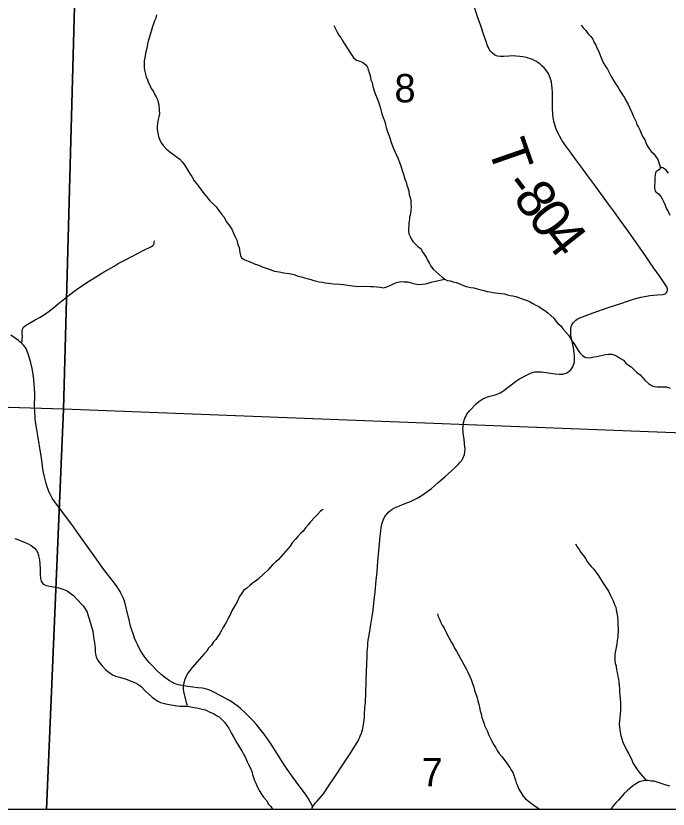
# Model space of a CAD drawing. Extents: x -3.3 to 34, y 0 to 56.8.
# Drawn here: x -0.484 to 0.477, y 28.077 to 29.247 of the extents above; entities that cross this region are included whole.
import ezdxf

# ---------------------------------------------------------------- set-up
doc = ezdxf.new("R2010")
doc.units = 0
for name, color, linetype in [('GM_X_Corporation', 7, 'Continuous'), ('GM_X_Section_Text', 7, 'Continuous'), ('GM_X_Township_Road', 7, 'Continuous'), ('GM_X_Township_Road_Text', 7, 'Continuous'), ('GT_Project_Soil_Layers', 7, 'Continuous'), ('SH_Data', 7, 'Continuous')]:
    doc.layers.add(name, color=color, linetype=linetype)

msp = doc.modelspace()

# ---------------------------------------------------------------- linework, layer by layer
at = {"layer": 'GM_X_Corporation'}
msp.add_lwpolyline([(-3.3039, 33.7379), (-3.3039, 28.0771), (1.5699, 28.0771), (1.5942, 28.7382), (1.6459, 29.8169), (1.6538, 30.0279), (1.685, 30.798), (1.6882, 30.9891), (1.6883, 30.9953), (1.6885, 31.0075), (1.698, 31.5661), (1.7459, 32.363)], dxfattribs=at)
for points in [[(-1.3918, 29.7067), (-0.3862, 29.675), (-0.4137, 28.6668), (-1.4193, 28.6974)], [(0.6247, 29.6418), (0.5878, 28.6278), (-0.4137, 28.6668), (-0.3862, 29.675)], [(-1.4478, 28.0771), (-0.4384, 28.0771), (-0.4137, 28.6668), (-1.4193, 28.6974)], [(-0.4384, 28.0771), (0.5667, 28.0771), (0.5878, 28.6278), (-0.4137, 28.6668)]]:
    msp.add_lwpolyline(points, close=True, dxfattribs=at)
at = {"layer": 'GM_X_Township_Road'}
for points in [[(-0.0464, 28.0803), (-0.0453, 28.0823), (-0.0437, 28.0845), (-0.0421, 28.0862), (-0.0399, 28.0886), (-0.0369, 28.092), (-0.0306, 28.0998), (-0.024, 28.1093), (-0.0127, 28.1263), (-0.0024, 28.1419), (0.0084, 28.1581), (0.0191, 28.1751), (0.0212, 28.1788), (0.0237, 28.1844), (0.0254, 28.1892), (0.0273, 28.1957), (0.0281, 28.199), (0.0291, 28.2055), (0.0298, 28.2122), (0.0302, 28.2169), (0.0307, 28.2257), (0.0313, 28.2348), (0.0318, 28.2481), (0.0325, 28.2655), (0.0331, 28.2799), (0.0339, 28.3033), (0.0341, 28.3086), (0.0345, 28.3134), (0.0347, 28.3174), (0.035, 28.3211), (0.0356, 28.3263), (0.0368, 28.3338), (0.0394, 28.3493), (0.0414, 28.361), (0.0426, 28.3703), (0.0438, 28.3807), (0.0456, 28.3976), (0.0473, 28.4143), (0.0485, 28.427), (0.0498, 28.4428), (0.0514, 28.4627), (0.053, 28.4797), (0.0539, 28.4876), (0.0546, 28.4924), (0.0557, 28.4971), (0.0571, 28.5017), (0.0582, 28.5048), (0.0597, 28.5078), (0.0614, 28.5104), (0.0627, 28.512), (0.0658, 28.5153), (0.0683, 28.5174), (0.0706, 28.5191), (0.0741, 28.5211), (0.0815, 28.5244), (0.091, 28.5282), (0.0951, 28.5297), (0.0985, 28.5312), (0.1034, 28.5335), (0.1075, 28.5357), (0.1151, 28.5402), (0.1185, 28.5425), (0.1238, 28.5463), (0.1285, 28.55), (0.1383, 28.5586), (0.1482, 28.5672), (0.1584, 28.576), (0.1645, 28.5816), (0.1681, 28.5852), (0.1706, 28.588), (0.1727, 28.5908), (0.1748, 28.5941), (0.1759, 28.5964), (0.1771, 28.6001), (0.1778, 28.6039), (0.1781, 28.6077), (0.1779, 28.6108), (0.1775, 28.6162), (0.1767, 28.6225), (0.1759, 28.6279), (0.1755, 28.6314), (0.1753, 28.6348), (0.1751, 28.638), (0.1752, 28.641), (0.1755, 28.645), (0.1761, 28.6479), (0.1768, 28.6507), (0.178, 28.6537), (0.1791, 28.6562), (0.1805, 28.6585), (0.1824, 28.6612), (0.1852, 28.6647), (0.1946, 28.6745), (0.1985, 28.678), (0.2014, 28.6801), (0.2044, 28.6819), (0.2079, 28.6835), (0.2129, 28.6854), (0.2188, 28.6869), (0.2225, 28.6878), (0.2253, 28.6887), (0.2278, 28.6898), (0.2301, 28.6909), (0.2323, 28.6922), (0.2352, 28.6945), (0.2461, 28.7029), (0.2525, 28.7076), (0.2585, 28.7114), (0.2706, 28.7179), (0.2737, 28.7194), (0.2761, 28.7204), (0.2788, 28.7212), (0.281, 28.7216), (0.2838, 28.7218), (0.287, 28.7218), (0.2905, 28.7216), (0.2944, 28.7213), (0.3111, 28.719), (0.3166, 28.7185), (0.3188, 28.7184), (0.3221, 28.7186), (0.325, 28.7193), (0.3269, 28.72), (0.3288, 28.7209), (0.3309, 28.7223), (0.3331, 28.7239), (0.3352, 28.7263), (0.3369, 28.7291), (0.3381, 28.7324), (0.3388, 28.7348), (0.3392, 28.7372), (0.3394, 28.7412), (0.3394, 28.745), (0.339, 28.7498), (0.3379, 28.7574), (0.3364, 28.7646), (0.3352, 28.7705), (0.3342, 28.7762), (0.3338, 28.78), (0.3339, 28.7856), (0.3345, 28.7884), (0.3356, 28.7909), (0.3375, 28.7939), (0.3394, 28.796), (0.3412, 28.7978), (0.3433, 28.7995), (0.3452, 28.8006), (0.3473, 28.8014), (0.3667, 28.8087), (0.389, 28.8165), (0.406, 28.8223), (0.4191, 28.8267), (0.4278, 28.8293), (0.437, 28.8318), (0.4456, 28.8336), (0.4506, 28.8343), (0.456, 28.8349), (0.4612, 28.8353), (0.4697, 28.8359), (0.4716, 28.8363), (0.4729, 28.8367), (0.474, 28.8376), (0.4749, 28.8387), (0.4758, 28.8405), (0.4763, 28.8424), (0.4764, 28.8441), (0.4761, 28.8456), (0.4756, 28.847), (0.4747, 28.8486), (0.4714, 28.8533), (0.4642, 28.8637), (0.4565, 28.8748), (0.4501, 28.8841), (0.4451, 28.8914), (0.4362, 28.9041), (0.4258, 28.9189), (0.4175, 28.9307), (0.4069, 28.9456), (0.3983, 28.9574), (0.3897, 28.969), (0.3792, 28.9834), (0.3687, 28.9977), (0.3588, 29.0111), (0.3497, 29.0235), (0.3409, 29.0355), (0.332, 29.0477), (0.3249, 29.0573), (0.323, 29.06), (0.3214, 29.0626), (0.3179, 29.0686), (0.3161, 29.0718), (0.3145, 29.0752), (0.312, 29.0809), (0.3108, 29.0845), (0.3098, 29.0879), (0.3091, 29.0907), (0.3086, 29.0937), (0.3081, 29.0966), (0.3075, 29.1019), (0.3072, 29.1099), (0.307, 29.125), (0.3069, 29.1342), (0.3066, 29.1401), (0.3062, 29.1444), (0.3055, 29.1487), (0.3047, 29.1522), (0.3038, 29.1551), (0.3027, 29.1579), (0.3009, 29.1615), (0.2992, 29.1643), (0.2973, 29.1671), (0.2947, 29.17), (0.2915, 29.1732), (0.2887, 29.1755), (0.2859, 29.1776), (0.2835, 29.1792), (0.281, 29.1806), (0.2775, 29.1823), (0.2745, 29.1835), (0.2713, 29.1845), (0.2685, 29.1852), (0.2635, 29.1862), (0.2591, 29.1869), (0.2536, 29.1875), (0.2499, 29.1876), (0.2353, 29.1869), (0.2325, 29.1868), (0.2297, 29.1869), (0.226, 29.1875), (0.2236, 29.1884), (0.2216, 29.1894), (0.2179, 29.192), (0.2155, 29.1948), (0.2141, 29.1968), (0.2125, 29.1999), (0.2113, 29.2026), (0.2097, 29.2073), (0.2054, 29.2199), (0.2013, 29.2319), (0.1967, 29.2453), (0.1914, 29.261)], [(-0.4757, 28.7643), (-0.4747, 28.7673), (-0.4743, 28.7699), (-0.4742, 28.7735), (-0.4744, 28.7787), (-0.4744, 28.7815), (-0.4742, 28.7838), (-0.4736, 28.7855), (-0.4723, 28.7875), (-0.47, 28.7897), (-0.4672, 28.7917), (-0.4553, 28.7985), (-0.4481, 28.8025), (-0.4416, 28.8065), (-0.4348, 28.8114), (-0.4279, 28.8167), (-0.4213, 28.8222), (-0.4117, 28.8301), (-0.3984, 28.8405), (-0.3931, 28.8444), (-0.3872, 28.8483), (-0.3777, 28.8543), (-0.3678, 28.8605), (-0.357, 28.8674), (-0.3391, 28.8778), (-0.3328, 28.8815), (-0.3234, 28.8867), (-0.313, 28.892), (-0.3036, 28.8968), (-0.2964, 28.9007), (-0.2839, 28.9068), (-0.2821, 28.908), (-0.2809, 28.9093), (-0.2801, 28.9109), (-0.2798, 28.9129), (-0.2796, 28.9152)], [(-0.0464, 28.0803), (-0.0501, 28.0876), (-0.0532, 28.0933), (-0.0559, 28.0975), (-0.0584, 28.1009), (-0.0692, 28.1155), (-0.0779, 28.1276), (-0.0872, 28.1409), (-0.1076, 28.1729), (-0.1177, 28.1874), (-0.1298, 28.2021), (-0.1338, 28.2066), (-0.146, 28.2188), (-0.1527, 28.2253), (-0.1561, 28.2283), (-0.161, 28.2319), (-0.1649, 28.2346), (-0.1691, 28.237), (-0.1919, 28.2494), (-0.1968, 28.2519), (-0.2008, 28.2534), (-0.2046, 28.2544), (-0.2087, 28.2552), (-0.2155, 28.2561), (-0.2306, 28.2579), (-0.2416, 28.2596), (-0.2446, 28.2603), (-0.2474, 28.2611), (-0.2507, 28.2625), (-0.2531, 28.2637), (-0.2575, 28.2664), (-0.2629, 28.2701), (-0.2696, 28.2756), (-0.2764, 28.2822), (-0.2831, 28.289), (-0.2872, 28.2932), (-0.2917, 28.2985), (-0.2949, 28.3026), (-0.2968, 28.3055), (-0.2996, 28.31), (-0.302, 28.3144), (-0.3041, 28.3186), (-0.3065, 28.3239), (-0.3088, 28.3293), (-0.311, 28.3354), (-0.3133, 28.3422), (-0.3147, 28.3467), (-0.3163, 28.3537), (-0.3203, 28.3701), (-0.3213, 28.374), (-0.3234, 28.3824), (-0.3252, 28.3876), (-0.3269, 28.3917), (-0.3289, 28.3956), (-0.3303, 28.398), (-0.332, 28.4007), (-0.3346, 28.4048), (-0.3383, 28.4101), (-0.354, 28.4302), (-0.3722, 28.456), (-0.3908, 28.4821), (-0.4015, 28.4967), (-0.4267, 28.5306), (-0.4302, 28.5358), (-0.4317, 28.5384), (-0.4322, 28.5393), (-0.4338, 28.5425), (-0.4356, 28.5467), (-0.4376, 28.5521), (-0.4391, 28.557), (-0.4418, 28.5672), (-0.4432, 28.5734), (-0.4439, 28.5786), (-0.4461, 28.5952), (-0.4473, 28.6035), (-0.4509, 28.6252), (-0.453, 28.6366), (-0.4548, 28.6481), (-0.4554, 28.6531), (-0.456, 28.6641), (-0.4561, 28.6694), (-0.4559, 28.6892), (-0.4562, 28.6976), (-0.4571, 28.7089), (-0.4578, 28.7151), (-0.4587, 28.7211), (-0.4597, 28.7269), (-0.4616, 28.7353), (-0.4635, 28.7421), (-0.4656, 28.7486), (-0.4669, 28.752), (-0.4688, 28.756), (-0.4702, 28.7582), (-0.4725, 28.7612), (-0.4757, 28.7643), (-0.4777, 28.766), (-0.4801, 28.7678), (-0.4911, 28.7759)], [(-0.0473, 28.0771), (-0.047, 28.079), (-0.0464, 28.0803)]]:
    msp.add_lwpolyline(points, dxfattribs=at)
at = {"layer": 'GT_Project_Soil_Layers'}
for points in [[(-0.2765, 29.2484), (-0.2776, 29.2434), (-0.2795, 29.2396), (-0.2809, 29.2347), (-0.2824, 29.2309), (-0.2838, 29.2255), (-0.2856, 29.2206), (-0.2889, 29.2095), (-0.29, 29.2053), (-0.2903, 29.2015), (-0.2914, 29.1973), (-0.2921, 29.1935), (-0.2935, 29.1852), (-0.2946, 29.1806), (-0.2945, 29.1711), (-0.294, 29.1666), (-0.2932, 29.1628), (-0.292, 29.1567), (-0.29, 29.1526), (-0.2889, 29.1488), (-0.2865, 29.1443), (-0.2842, 29.1394), (-0.2811, 29.1353), (-0.2795, 29.1311), (-0.2772, 29.1273), (-0.2752, 29.1232), (-0.274, 29.119), (-0.2732, 29.1153), (-0.2724, 29.1077), (-0.2723, 29.102), (-0.273, 29.0978), (-0.2744, 29.0917), (-0.2751, 29.0879), (-0.2755, 29.0837), (-0.2754, 29.0792), (-0.2734, 29.069), (-0.2714, 29.0633), (-0.2694, 29.0592), (-0.2667, 29.0554), (-0.2617, 29.0502), (-0.2568, 29.0461), (-0.2476, 29.0394), (-0.2422, 29.0353), (-0.238, 29.0311), (-0.236, 29.0274), (-0.2326, 29.0229), (-0.2294, 29.0172), (-0.2271, 29.0135), (-0.2244, 29.0097), (-0.2209, 29.0033), (-0.2178, 28.9995), (-0.2147, 28.9954), (-0.2066, 28.9849), (-0.2032, 28.9808), (-0.1978, 28.974), (-0.1935, 28.9699), (-0.1893, 28.9654), (-0.1847, 28.9598), (-0.1808, 28.9545), (-0.177, 28.95), (-0.1738, 28.9436), (-0.17, 28.9387), (-0.1657, 28.932), (-0.163, 28.9263), (-0.1603, 28.9199), (-0.1583, 28.9161), (-0.1567, 28.9097), (-0.1547, 28.9052), (-0.1535, 28.898), (-0.1527, 28.8935), (-0.1511, 28.8897), (-0.1462, 28.8871), (-0.1416, 28.8849), (-0.1374, 28.8834), (-0.1309, 28.8805), (-0.1256, 28.879), (-0.1206, 28.8768), (-0.1149, 28.8746), (-0.1092, 28.8728), (-0.1027, 28.8703), (-0.0959, 28.8692), (-0.089, 28.8678), (-0.0807, 28.8668), (-0.0742, 28.8653), (-0.0677, 28.8628), (-0.0628, 28.8617), (-0.0586, 28.8602), (-0.0525, 28.8592), (-0.0411, 28.8556), (-0.0369, 28.8545), (-0.032, 28.8538), (-0.0278, 28.8531), (-0.0232, 28.8528), (-0.0194, 28.8521), (-0.0156, 28.8517), (-0.0065, 28.8511), (-0.0012, 28.8508), (0.0049, 28.8497), (0.0087, 28.849)], [(-0.0151, 29.2323), (-0.0104, 29.2225), (-0.008, 29.2184), (-0.005, 29.2146), (-0.003, 29.2108), (-0.0007, 29.2067), (0.0024, 29.2026), (0.0047, 29.1984), (0.0082, 29.1932), (0.0113, 29.1887), (0.014, 29.1849), (0.0182, 29.1815), (0.0232, 29.1797), (0.0274, 29.1779), (0.0316, 29.1749), (0.0343, 29.1711), (0.0355, 29.167), (0.0367, 29.1632), (0.0383, 29.1587), (0.0395, 29.1522), (0.0411, 29.1485), (0.0423, 29.1424), (0.0454, 29.1333), (0.0486, 29.125), (0.0509, 29.1186), (0.0521, 29.1148), (0.0533, 29.1103), (0.0557, 29.1024), (0.0577, 29.0967), (0.06, 29.0907), (0.0609, 29.0858), (0.0621, 29.082), (0.0632, 29.0774), (0.0656, 29.0706), (0.0672, 29.0669), (0.0692, 29.0601), (0.0715, 29.0537), (0.0747, 29.0465), (0.0774, 29.0405), (0.0797, 29.0359), (0.0809, 29.0322), (0.0837, 29.0254), (0.0857, 29.0186), (0.0876, 29.0133), (0.0892, 29.0057), (0.0912, 29.0016), (0.0924, 28.997), (0.0944, 28.9917), (0.0952, 28.988), (0.096, 28.983), (0.0972, 28.9789), (0.098, 28.9747), (0.0984, 28.9706), (0.0985, 28.9656), (0.0982, 28.9599), (0.0979, 28.955), (0.0964, 28.9504), (0.0961, 28.9462), (0.0954, 28.9417), (0.0951, 28.9371), (0.0948, 28.9333), (0.0948, 28.9291), (0.0953, 28.9254), (0.0972, 28.9216), (0.0988, 28.9178), (0.1011, 28.9141), (0.1053, 28.9103), (0.1088, 28.9066), (0.1134, 28.9032), (0.1149, 28.8994), (0.118, 28.8953), (0.1207, 28.8908), (0.1227, 28.8863), (0.1258, 28.8818), (0.1277, 28.8776), (0.1312, 28.8731), (0.14, 28.8653), (0.1443, 28.8612), (0.1481, 28.8585), (0.1519, 28.8567), (0.1561, 28.856), (0.1607, 28.8545), (0.1649, 28.8535), (0.169, 28.852), (0.1782, 28.8483), (0.182, 28.8473), (0.1866, 28.8462), (0.1911, 28.8455), (0.2014, 28.8426), (0.2063, 28.8419), (0.2109, 28.8404), (0.2147, 28.8397), (0.2193, 28.839), (0.2231, 28.8383), (0.2269, 28.838), (0.2314, 28.8373), (0.2364, 28.8366), (0.2409, 28.8355), (0.2447, 28.8345), (0.2485, 28.8338), (0.2531, 28.8327)], [(0.3493, 29.2328), (0.3524, 29.229), (0.3563, 29.2253), (0.3597, 29.2204), (0.3636, 29.2163), (0.3663, 29.2121), (0.3686, 29.2076), (0.371, 29.2035), (0.3722, 29.1997), (0.3745, 29.1959), (0.3761, 29.191), (0.3792, 29.1839), (0.3823, 29.1771), (0.3847, 29.1729), (0.3878, 29.168), (0.3916, 29.1613), (0.3936, 29.1571), (0.3971, 29.1515), (0.4002, 29.1458), (0.4037, 29.1409), (0.4064, 29.1364), (0.4103, 29.1304), (0.4133, 29.1263), (0.4149, 29.1221), (0.4184, 29.1161), (0.4208, 29.1104), (0.4239, 29.1044), (0.4258, 29.0995), (0.4301, 29.0905), (0.4313, 29.0867), (0.4337, 29.0825), (0.4356, 29.0788), (0.4376, 29.0739), (0.4407, 29.0675), (0.443, 29.0637), (0.4458, 29.0562), (0.4489, 29.0516), (0.4523, 29.0468), (0.4562, 29.0434), (0.4589, 29.0396), (0.4623, 29.0351), (0.4663, 29.0226)], [(0.4671, 29.0234), (0.4637, 29.0196), (0.4592, 29.0165), (0.4581, 29.0127), (0.4578, 29.0081), (0.4579, 29.0017), (0.4575, 28.9975), (0.4572, 28.9926), (0.4584, 28.988), (0.463, 28.9843), (0.4665, 28.9805), (0.4684, 28.9768), (0.4712, 28.9719), (0.4731, 28.9677), (0.4747, 28.9632), (0.477, 28.9594), (0.4798, 28.953)], [(0.4778, 29.0149), (0.4743, 29.019), (0.4705, 29.0223), (0.4671, 29.0234)], [(0.0087, 28.849), (0.0125, 28.8487), (0.0167, 28.848), (0.0205, 28.8477), (0.0341, 28.8479), (0.039, 28.8476), (0.0432, 28.8476), (0.0481, 28.8473), (0.0531, 28.8466), (0.058, 28.8459), (0.0629, 28.8471), (0.0678, 28.8491), (0.0727, 28.8518), (0.0773, 28.8534), (0.081, 28.8546), (0.0848, 28.855), (0.0886, 28.8547), (0.0932, 28.8544), (0.0985, 28.8529), (0.1023, 28.8522), (0.1069, 28.8511), (0.111, 28.8508), (0.1156, 28.8509), (0.1201, 28.8517), (0.1239, 28.8525), (0.1284, 28.8541), (0.1479, 28.8587)], [(0.2531, 28.8327), (0.2569, 28.8316), (0.2607, 28.8301), (0.2653, 28.8287), (0.2695, 28.8272), (0.2741, 28.825), (0.2779, 28.8228), (0.2825, 28.8202), (0.2867, 28.818), (0.2909, 28.815), (0.2955, 28.8124), (0.3001, 28.809), (0.3047, 28.8049), (0.3093, 28.8004), (0.312, 28.7967), (0.3155, 28.7926), (0.3193, 28.7896), (0.3224, 28.7854), (0.3266, 28.7802), (0.3305, 28.7761), (0.3328, 28.7719), (0.3351, 28.7682), (0.339, 28.7629), (0.3417, 28.7584), (0.3448, 28.7535), (0.3471, 28.7497), (0.351, 28.746), (0.3559, 28.743), (0.3601, 28.7423), (0.3639, 28.7428), (0.3681, 28.744), (0.3722, 28.7444), (0.3764, 28.7452), (0.3805, 28.7464), (0.3851, 28.7476), (0.3896, 28.748), (0.3942, 28.7477), (0.3987, 28.7463), (0.4029, 28.7444), (0.4072, 28.7415), (0.4114, 28.7389), (0.4152, 28.7347), (0.419, 28.7318), (0.4229, 28.7292), (0.4267, 28.7254), (0.4306, 28.7213), (0.4363, 28.7172), (0.4432, 28.7097), (0.4486, 28.7048), (0.4528, 28.7015), (0.4566, 28.7004), (0.4612, 28.6997), (0.4665, 28.6998), (0.471, 28.6995), (0.4752, 28.6995), (0.4802, 28.6977)], [(-0.0311, 28.519), (-0.0349, 28.5163), (-0.0394, 28.5117), (-0.0436, 28.5071), (-0.0496, 28.5006), (-0.053, 28.496), (-0.0572, 28.4918), (-0.0605, 28.4868), (-0.0643, 28.4837), (-0.0685, 28.4791), (-0.0715, 28.4753), (-0.0764, 28.4695), (-0.0794, 28.4646), (-0.0832, 28.4611), (-0.0865, 28.4569), (-0.0899, 28.4531), (-0.0933, 28.4492), (-0.0967, 28.445), (-0.1005, 28.4419), (-0.1054, 28.4373), (-0.1088, 28.4331), (-0.1126, 28.4296), (-0.1179, 28.4246), (-0.1269, 28.4162), (-0.1307, 28.4131), (-0.1349, 28.4104), (-0.139, 28.4069), (-0.1436, 28.4031), (-0.1481, 28.3996), (-0.1515, 28.3943), (-0.1545, 28.3901), (-0.1564, 28.3855), (-0.1597, 28.3794), (-0.162, 28.3752), (-0.165, 28.3702), (-0.168, 28.3633), (-0.1713, 28.3572), (-0.1736, 28.3534), (-0.1755, 28.3496), (-0.1788, 28.3442), (-0.1811, 28.3396), (-0.1833, 28.3358), (-0.186, 28.3316), (-0.1893, 28.3274), (-0.1924, 28.3235), (-0.1957, 28.319), (-0.1999, 28.3143), (-0.2025, 28.3098), (-0.2063, 28.3059), (-0.2131, 28.2983), (-0.224, 28.286), (-0.227, 28.2821), (-0.2304, 28.2775), (-0.2327, 28.2733), (-0.2349, 28.2684), (-0.2364, 28.2634), (-0.2371, 28.2589), (-0.2374, 28.2547), (-0.2366, 28.2501), (-0.2314, 28.2287)], [(-0.4855, 28.4761), (-0.4809, 28.4746), (-0.4717, 28.4709), (-0.4668, 28.4687), (-0.4614, 28.4657), (-0.4568, 28.4623), (-0.4533, 28.4586), (-0.4514, 28.4548), (-0.4502, 28.4506), (-0.449, 28.4445), (-0.4481, 28.4312), (-0.4481, 28.4229), (-0.4473, 28.4172), (-0.4465, 28.413), (-0.4434, 28.4089), (-0.4384, 28.407), (-0.4285, 28.4048), (-0.4243, 28.4041), (-0.4189, 28.403), (-0.4132, 28.4008), (-0.4082, 28.399), (-0.4036, 28.3956), (-0.3987, 28.3922), (-0.3948, 28.3877), (-0.3844, 28.3768), (-0.3817, 28.3722), (-0.3786, 28.3673), (-0.3774, 28.362), (-0.3759, 28.3578), (-0.3739, 28.351), (-0.3727, 28.3472), (-0.3715, 28.3431), (-0.3704, 28.3393), (-0.3695, 28.3313), (-0.3687, 28.3271), (-0.3679, 28.3226), (-0.3675, 28.3188), (-0.3667, 28.3138), (-0.3667, 28.3093), (-0.3663, 28.3055), (-0.3655, 28.3017), (-0.3631, 28.296), (-0.3573, 28.2888), (-0.3512, 28.2824), (-0.347, 28.279), (-0.3412, 28.2749), (-0.337, 28.2731), (-0.3332, 28.272), (-0.3294, 28.2712), (-0.324, 28.2698), (-0.3198, 28.2683), (-0.3114, 28.2646), (-0.3076, 28.2631), (-0.3038, 28.2612), (-0.2992, 28.2579), (-0.293, 28.2515), (-0.2876, 28.2466), (-0.283, 28.2421), (-0.2788, 28.2394), (-0.2746, 28.2364), (-0.2708, 28.2342), (-0.2666, 28.2331), (-0.2628, 28.2324), (-0.2578, 28.2313), (-0.2463, 28.2295), (-0.2422, 28.2288), (-0.2334, 28.2289), (-0.2284, 28.2285), (-0.2212, 28.2271), (-0.217, 28.2264), (-0.2132, 28.2253), (-0.209, 28.2245), (-0.2044, 28.2234), (-0.1987, 28.2205), (-0.1925, 28.2179), (-0.1883, 28.2152), (-0.1841, 28.213), (-0.1799, 28.2089), (-0.176, 28.2047), (-0.173, 28.2002), (-0.1699, 28.1964), (-0.1664, 28.1896), (-0.1629, 28.1836), (-0.1606, 28.179)], [(0.3411, 28.4683), (0.3434, 28.4637), (0.3461, 28.46), (0.3488, 28.4554), (0.3523, 28.4513), (0.3554, 28.4464), (0.3581, 28.4422), (0.3608, 28.4384), (0.3642, 28.4347), (0.3681, 28.4309), (0.3715, 28.426), (0.3754, 28.4207), (0.3808, 28.4116), (0.3847, 28.406), (0.3893, 28.3984), (0.392, 28.3931), (0.3943, 28.3882), (0.3963, 28.3844), (0.3982, 28.3787), (0.4002, 28.3749), (0.401, 28.3711), (0.4026, 28.3613), (0.4034, 28.3533), (0.4036, 28.3392), (0.4032, 28.3347), (0.4032, 28.3309), (0.4025, 28.3255), (0.4018, 28.3206), (0.4007, 28.3156), (0.4, 28.3107), (0.3989, 28.3057), (0.399, 28.2959), (0.3994, 28.2921), (0.4006, 28.2879), (0.4014, 28.2826), (0.4022, 28.2784), (0.4034, 28.2727), (0.4042, 28.2685), (0.4046, 28.2647), (0.405, 28.2594), (0.4058, 28.2545), (0.4059, 28.2503), (0.4063, 28.2454), (0.4067, 28.2393), (0.4072, 28.2351), (0.4073, 28.2222), (0.4069, 28.2176), (0.4062, 28.2123), (0.4055, 28.2073), (0.4052, 28.202), (0.4056, 28.1982), (0.4064, 28.1944), (0.4068, 28.1906), (0.4076, 28.1857), (0.4107, 28.1758), (0.4127, 28.1713), (0.415, 28.1668), (0.417, 28.1626), (0.4193, 28.1584), (0.4212, 28.1543), (0.4232, 28.1505), (0.4259, 28.1444), (0.429, 28.1399), (0.4317, 28.1357), (0.434, 28.132), (0.4448, 28.1191)], [(0.1375, 28.3648), (0.1387, 28.361), (0.1406, 28.3572), (0.1422, 28.3531), (0.1445, 28.3485), (0.1472, 28.344), (0.1515, 28.3357), (0.1584, 28.3228), (0.1607, 28.3186), (0.1627, 28.3145), (0.1654, 28.3099), (0.1685, 28.3047), (0.1716, 28.299), (0.177, 28.2891), (0.1797, 28.2839), (0.1821, 28.2789), (0.1852, 28.2725), (0.1871, 28.268), (0.1891, 28.2623), (0.191, 28.257), (0.1926, 28.2505), (0.1945, 28.2456), (0.1961, 28.2414), (0.1969, 28.2365), (0.1985, 28.2312), (0.1993, 28.2274), (0.2005, 28.2221), (0.2017, 28.2175), (0.2029, 28.2122), (0.2044, 28.2084), (0.2056, 28.2043), (0.2072, 28.1993), (0.2091, 28.1956), (0.2114, 28.1914), (0.2126, 28.1872), (0.2153, 28.1823), (0.2173, 28.1782), (0.2207, 28.1721), (0.2234, 28.1676), (0.2254, 28.1634), (0.2285, 28.1593), (0.2323, 28.1547), (0.235, 28.151), (0.2381, 28.1468), (0.2412, 28.1423), (0.2439, 28.1385), (0.2466, 28.134), (0.2489, 28.1302), (0.2505, 28.1256), (0.2524, 28.1196), (0.2536, 28.1158), (0.2552, 28.112), (0.2567, 28.1074), (0.2637, 28.0961), (0.2672, 28.0923), (0.2714, 28.0886), (0.276, 28.0852), (0.2878, 28.0771)], [(-0.1606, 28.179), (-0.1583, 28.1749), (-0.1559, 28.1711), (-0.1528, 28.1662), (-0.1501, 28.162), (-0.1482, 28.1582), (-0.1459, 28.1541), (-0.1428, 28.1469), (-0.1408, 28.1431), (-0.1385, 28.1382), (-0.1362, 28.1325), (-0.135, 28.1279), (-0.1322, 28.1192), (-0.1303, 28.1154), (-0.1287, 28.1117), (-0.1268, 28.1075), (-0.1245, 28.103), (-0.1214, 28.098), (-0.1183, 28.0943), (-0.1144, 28.0898), (-0.1113, 28.0845), (-0.1079, 28.0807), (-0.1058, 28.0771)], [(0.4799, 28.1111), (0.4745, 28.1126), (0.4703, 28.1137), (0.4566, 28.1181), (0.4524, 28.1185), (0.4478, 28.1192), (0.4433, 28.1191), (0.4387, 28.1183), (0.4349, 28.1175), (0.4292, 28.1141), (0.425, 28.111)], [(0.425, 28.111), (0.4209, 28.1075), (0.4171, 28.1041), (0.4126, 28.1002), (0.4043, 28.0902), (0.4005, 28.0864), (0.3971, 28.0826), (0.3941, 28.0784), (0.3929, 28.0771)]]:
    msp.add_lwpolyline(points, dxfattribs=at)
at = {"layer": 'SH_Data'}
msp.add_line((-3.3039, 28.0771), (3.4961, 28.0771), dxfattribs=at)

# ---------------------------------------------------------------- texts
at = {"layer": 'GM_X_Section_Text'}
for s, p in [('8', (0.0741, 29.1191)), ('7', (0.1141, 28.1105))]:
    msp.add_text(s, height=0.0419, rotation=0, dxfattribs=at).set_placement(p)
at = {"layer": 'GM_X_Township_Road_Text'}
for s, rotation, p in [('T', 289.1783, (0.2109, 29.0531)), ('-', 306.8078, (0.2338, 28.9962)), ('8', 305.828, (0.2476, 28.9778)), ('0', 307.1294, (0.2689, 28.9482)), ('4', 308.2504, (0.2908, 28.9194))]:
    msp.add_text(s, height=0.0568, rotation=rotation, dxfattribs=at).set_placement(p)

doc.saveas('drawing.dxf')
